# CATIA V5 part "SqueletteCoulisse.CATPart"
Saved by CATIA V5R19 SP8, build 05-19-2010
Part number: SqueletteCoulisse
Bounding box of the stored display mesh (mm): x 0 to 40, y 28 to 91, z 60 to 60
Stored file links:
  C:\Users\rcousturie\Desktop\EU_thinkMotion\iao\IAO_MMS_Groupe1\abergami\abergami_catiaInitial\ObjetsInitials\SqueletteCoulisse.CATPart
  C:\Users\rcousturie\Desktop\EU_thinkMotion\iao\IAO_MMS_Groupe1\abergami\abergami_catiaInitial\ObjetsInitials\Product2.CATProduct
  C:\Users\rcousturie\Desktop\EU_thinkMotion\iao\IAO_MMS_Groupe1\abergami\abergami_catiaInitial\ObjetsInitials\Squelettedebase.CATPart
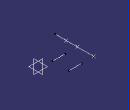
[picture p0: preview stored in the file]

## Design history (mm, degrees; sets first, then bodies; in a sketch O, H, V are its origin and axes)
Set1
  Point1 to Point3: linked copy from another document
Body1 (main body)
  Line1: type Normal, RefPoint Point1, RefSkin yz-plane, Start 20, End 40
  Line2: type PtPt, FirstPoint Point1, SecondPoint Point3, End 18
  Line3: type PtDir, RefPoint Point2, Direction yz-plane, Start 20, End 40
